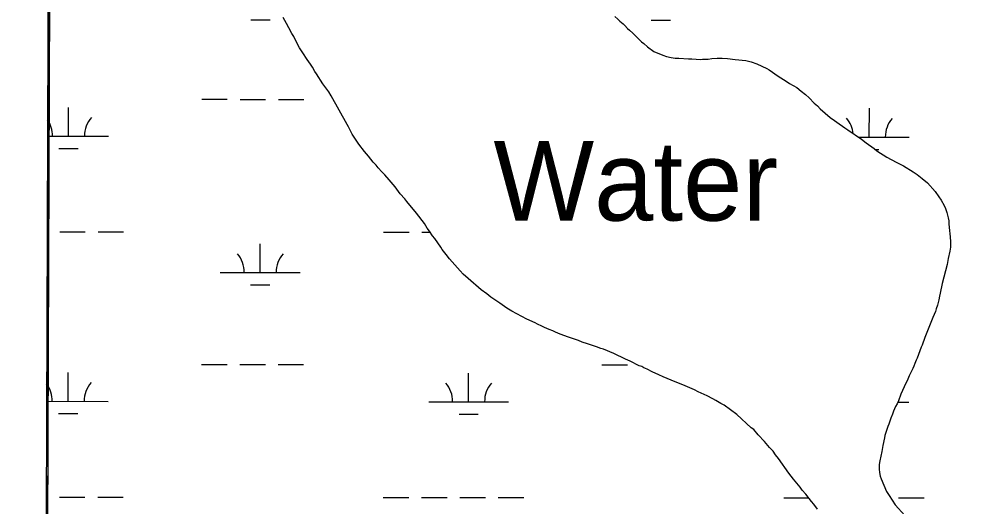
# Model space of a CAD drawing. Extents: x 3148686 to 3186545, y 916144 to 941516.
# Drawn here: x 3152922 to 3154122, y 931623 to 932235 of the extents above; entities that cross this region are included whole.
import ezdxf

# ---------------------------------------------------------------- set-up
doc = ezdxf.new("R2010")
doc.units = 0
for name, color, linetype in [('V-GRID-FRAM', 7, 'Continuous'), ('V-RIVR-IDEN', 7, 'Continuous'), ('V-SITE-VEGE', 7, 'Continuous'), ('V-TOPO-SHOR', 7, 'Continuous'), ('V-WETL-SWMP', 7, 'Continuous')]:
    doc.layers.add(name, color=color, linetype=linetype)

msp = doc.modelspace()

# ---------------------------------------------------------------- linework, layer by layer
at = {"layer": 'V-GRID-FRAM'}
msp.add_lwpolyline([(3152987.2, 939742.7), (3184296.3, 939644.8), (3184247.4, 921455.8), (3152922.4, 921553.7), (3152987.2, 939742.7)], dxfattribs=at)
at = {"layer": 'V-SITE-VEGE'}
for p, q in [((3152962, 932689.1), (3152952.2, 929936.2)), ((3153257.5, 932229.3), (3153253.5, 932237.1)), ((3153672.9, 932234.9), (3153675.3, 932232.5)), ((3153675.3, 932232.5), (3153679.4, 932229.1)), ((3153260.6, 932224.1), (3153257.5, 932229.3)), ((3153264.2, 932217), (3153260.6, 932224.1)), ((3153679.4, 932229.1), (3153681.7, 932226.7)), ((3153681.7, 932226.7), (3153684.8, 932223.2)), ((3153684.8, 932223.2), (3153687.5, 932221.2)), ((3153687.5, 932221.2), (3153691.8, 932217.1)), ((3153266.6, 932212.9), (3153264.2, 932217)), ((3153270.9, 932204.3), (3153266.6, 932212.9)), ((3153691.8, 932217.1), (3153702.3, 932206.4)), ((3153273.9, 932198.9), (3153270.9, 932204.3)), ((3153278, 932192.4), (3153273.9, 932198.9)), ((3153702.3, 932206.4), (3153705.3, 932204.4)), ((3153705.3, 932204.4), (3153710.1, 932200.3)), ((3153710.1, 932200.3), (3153717.8, 932194.4)), ((3153283.3, 932184.2), (3153278, 932192.4)), ((3153287.7, 932178.4), (3153283.3, 932184.2)), ((3153717.8, 932194.4), (3153729.3, 932189.6)), ((3153729.3, 932189.6), (3153733.8, 932188.2)), ((3153733.8, 932188.2), (3153739.5, 932186.8)), ((3153739.5, 932186.8), (3153744.6, 932186)), ((3153744.6, 932186), (3153749.4, 932186)), ((3153749.4, 932186), (3153761.6, 932184.9)), ((3153761.6, 932184.9), (3153765.7, 932184.9)), ((3153765.7, 932184.9), (3153771.1, 932184.5)), ((3153771.1, 932184.5), (3153775.9, 932184.4)), ((3153775.9, 932184.4), (3153778.9, 932184.7)), ((3153778.9, 932184.7), (3153786.1, 932184.7)), ((3153786.1, 932184.7), (3153790.5, 932185.3)), ((3153790.5, 932185.3), (3153797.3, 932186)), ((3153797.3, 932186), (3153803.4, 932185.9)), ((3153803.4, 932185.9), (3153810.2, 932185.5)), ((3153810.2, 932185.5), (3153819.7, 932184.1)), ((3153819.7, 932184.1), (3153833.3, 932182.9)), ((3153290.1, 932174.6), (3153287.7, 932178.4)), ((3153293.1, 932169.1), (3153290.1, 932174.6)), ((3153833.3, 932182.9), (3153840.1, 932181.2)), ((3153840.1, 932181.2), (3153847.2, 932178.7)), ((3153847.2, 932178.7), (3153859.4, 932172.9)), ((3153859.4, 932172.9), (3153862.5, 932171.1)), ((3153295.1, 932166.4), (3153293.1, 932169.1)), ((3153303.2, 932153.8), (3153295.1, 932166.4)), ((3153862.5, 932171.1), (3153873.9, 932163.2)), ((3153873.9, 932163.2), (3153883.8, 932157)), ((3153307.9, 932146.9), (3153303.2, 932153.8)), ((3153883.8, 932157), (3153887.8, 932154.3)), ((3153887.8, 932154.3), (3153897, 932149.1)), ((3153897, 932149.1), (3153902.7, 932144.6)), ((3153310.5, 932143.5), (3153307.9, 932146.9)), ((3153313.6, 932138.7), (3153310.5, 932143.5)), ((3153333.4, 932102.5), (3153313.6, 932138.7)), ((3153902.7, 932144.6), (3153908.1, 932140.2)), ((3153908.1, 932140.2), (3153912.5, 932136.1)), ((3153912.5, 932136.1), (3153918.9, 932129.5)), ((3153918.9, 932129.5), (3153922.9, 932126.1)), ((3153922.9, 932126.1), (3153926.6, 932122.3)), ((3153926.6, 932122.3), (3153939.1, 932111.4)), ((3153335, 932099.7), (3153333.4, 932102.5)), ((3153339.7, 932090.5), (3153335, 932099.7)), ((3153939.1, 932111.4), (3153944.2, 932107.9)), ((3153944.2, 932107.9), (3153947.2, 932105.5)), ((3153947.2, 932105.5), (3153957.4, 932098.6)), ((3153348.1, 932077.9), (3153339.7, 932090.5)), ((3153957.4, 932098.6), (3153961.1, 932095.9)), ((3153961.1, 932095.9), (3153978.3, 932084.2)), ((3153355.2, 932069), (3153348.1, 932077.9)), ((3153978.3, 932084.2), (3153984.1, 932079.7)), ((3153984.1, 932079.7), (3153994.2, 932072.5)), ((3153360.2, 932063.1), (3153355.2, 932069)), ((3153994.2, 932072.5), (3153997.6, 932069.8)), ((3153997.6, 932069.8), (3154010.1, 932061.5)), ((3153366, 932055.6), (3153360.2, 932063.1)), ((3153369.7, 932051.8), (3153366, 932055.6)), ((3153372.4, 932048.4), (3153369.7, 932051.8)), ((3154010.1, 932061.5), (3154021.6, 932055.3)), ((3154021.6, 932055.3), (3154030.8, 932050.8)), ((3153377.1, 932043.3), (3153372.4, 932048.4)), ((3153380.8, 932039.5), (3153377.1, 932043.3)), ((3153386.2, 932033.4), (3153380.8, 932039.5)), ((3154030.8, 932050.8), (3154042.9, 932043.5)), ((3154042.9, 932043.5), (3154048, 932040.1)), ((3154048, 932040.1), (3154054.4, 932035)), ((3153393.6, 932024.5), (3153386.2, 932033.4)), ((3154054.4, 932035), (3154060.8, 932029.5)), ((3154060.8, 932029.5), (3154070.6, 932018.5)), ((3153400, 932015.9), (3153393.6, 932024.5)), ((3153405.7, 932009.4), (3153400, 932015.9)), ((3154070.6, 932018.5), (3154075, 932012)), ((3153408.4, 932006), (3153405.7, 932009.4)), ((3153420.5, 931991.6), (3153408.4, 932006)), ((3154075, 932012), (3154078, 932007.9)), ((3154078, 932007.9), (3154082, 932001.1)), ((3153423.2, 931987.8), (3153420.5, 931991.6)), ((3154082, 932001.1), (3154083.7, 931997.3)), ((3154083.7, 931997.3), (3154085.4, 931992.2)), ((3154085.4, 931992.2), (3154087, 931985.4)), ((3153427.6, 931982.4), (3153423.2, 931987.8)), ((3153430.3, 931978.6), (3153427.6, 931982.4)), ((3154087, 931985.4), (3154087.7, 931982)), ((3154087.7, 931982), (3154087.6, 931977.9)), ((3153433.9, 931972.8), (3153430.3, 931978.6)), ((3153436.6, 931969), (3153433.9, 931972.8)), ((3153440.7, 931962.9), (3153436.6, 931969)), ((3154087.6, 931977.9), (3154088.3, 931973.5)), ((3154088.3, 931973.5), (3154089.2, 931961.6)), ((3153443.4, 931959.5), (3153440.7, 931962.9)), ((3153451.1, 931948.9), (3153443.4, 931959.5)), ((3154089.2, 931961.6), (3154089.8, 931955.5)), ((3153452.8, 931945.8), (3153451.1, 931948.9)), ((3153457.8, 931939.6), (3153452.8, 931945.8)), ((3154089, 931943.6), (3154086.9, 931934.7)), ((3154089.8, 931948.7), (3154089, 931943.6)), ((3154089.8, 931955.5), (3154089.8, 931948.7)), ((3153461.8, 931934.2), (3153457.8, 931939.6)), ((3153475, 931919.1), (3153461.8, 931934.2)), ((3154086.9, 931934.7), (3154085.5, 931926.9)), ((3154085.5, 931926.9), (3154079.5, 931903.2)), ((3153479, 931915), (3153475, 931919.1)), ((3153485.1, 931909.5), (3153479, 931915)), ((3153501.6, 931895.4), (3153485.1, 931909.5)), ((3154079.5, 931903.2), (3154077, 931891)), ((3153508.7, 931890.3), (3153501.6, 931895.4)), ((3153513.5, 931886.1), (3153508.7, 931890.3)), ((3153525, 931878.6), (3153513.5, 931886.1)), ((3154076, 931887.2), (3154075.3, 931882.8)), ((3154077, 931891), (3154076, 931887.2)), ((3153533.7, 931872.4), (3153525, 931878.6)), ((3153539.8, 931868.6), (3153533.7, 931872.4)), ((3154073.5, 931876), (3154071.8, 931871.3)), ((3154075.3, 931882.8), (3154073.5, 931876)), ((3153558.8, 931858.6), (3153539.8, 931868.6)), ((3154067.6, 931860.5), (3154057.6, 931835.4)), ((3154071.1, 931868.2), (3154067.6, 931860.5)), ((3154071.8, 931871.3), (3154071.1, 931868.2)), ((3153569, 931853.7), (3153558.8, 931858.6)), ((3153572, 931852), (3153569, 931853.7)), ((3153577.4, 931849.6), (3153572, 931852)), ((3153580.8, 931847.9), (3153577.4, 931849.6)), ((3153586.6, 931845.4), (3153580.8, 931847.9)), ((3153591.3, 931843.7), (3153586.6, 931845.4)), ((3153594.7, 931842), (3153591.3, 931843.7)), ((3153600.4, 931839.5), (3153594.7, 931842)), ((3153611, 931835.7), (3153600.4, 931839.5)), ((3153623.5, 931831.5), (3153611, 931835.7)), ((3153628.2, 931829.8), (3153623.5, 931831.5)), ((3153635, 931827.7), (3153628.2, 931829.8)), ((3153646.2, 931823.9), (3153635, 931827.7)), ((3153651.3, 931821.8), (3153646.2, 931823.9)), ((3154054.4, 931825.9), (3154053, 931823.2)), ((3154057.6, 931835.4), (3154054.4, 931825.9)), ((3153654.7, 931820.7), (3153651.3, 931821.8)), ((3153667.6, 931815.2), (3153654.7, 931820.7)), ((3153682.5, 931808.3), (3153667.6, 931815.2)), ((3154053, 931823.2), (3154048.2, 931809.6)), ((3153688.2, 931805.8), (3153682.5, 931808.3)), ((3153699.7, 931800), (3153688.2, 931805.8)), ((3153702.7, 931799.2), (3153699.7, 931800)), ((3154045.1, 931802.9), (3154043.7, 931799.5)), ((3154046.8, 931806.9), (3154045.1, 931802.9)), ((3154048.2, 931809.6), (3154046.8, 931806.9)), ((3153705.4, 931797.5), (3153702.7, 931799.2)), ((3153709.5, 931795.7), (3153705.4, 931797.5)), ((3153715.9, 931792.3), (3153709.5, 931795.7)), ((3153724.4, 931788.8), (3153715.9, 931792.3)), ((3153729.8, 931786.1), (3153724.4, 931788.8)), ((3154042.6, 931796.4), (3154038.1, 931787.3)), ((3154043.7, 931799.5), (3154042.6, 931796.4)), ((3153739.6, 931781.9), (3153729.8, 931786.1)), ((3153757.2, 931775), (3153739.6, 931781.9)), ((3154036.4, 931783.2), (3154031.9, 931773.7)), ((3154038.1, 931787.3), (3154036.4, 931783.2)), ((3153769.1, 931769.8), (3153757.2, 931775)), ((3153773.5, 931767.3), (3153769.1, 931769.8)), ((3153785, 931762.1), (3153773.5, 931767.3)), ((3154027.7, 931764.2), (3154024.6, 931756.1)), ((3154031.9, 931773.7), (3154027.7, 931764.2)), ((3153791.8, 931758.7), (3153785, 931762.1)), ((3153795.5, 931756.3), (3153791.8, 931758.7)), ((3153801.9, 931752.5), (3153795.5, 931756.3)), ((3153806, 931750.4), (3153801.9, 931752.5)), ((3154022.9, 931752.4), (3154020.8, 931749)), ((3154024.6, 931756.1), (3154022.9, 931752.4)), ((3153814.1, 931744.9), (3153806, 931750.4)), ((3153821.9, 931738.7), (3153814.1, 931744.9)), ((3154018.4, 931743.2), (3154017, 931739.2)), ((3154020.8, 931749), (3154018.4, 931743.2)), ((3153840.1, 931722.3), (3153821.9, 931738.7)), ((3154014.9, 931734.1), (3154012.5, 931726.6)), ((3154017, 931739.2), (3154014.9, 931734.1)), ((3153843.5, 931719.9), (3153840.1, 931722.3)), ((3153848.9, 931713.4), (3153843.5, 931719.9)), ((3154011.1, 931723.6), (3154007.6, 931712.7)), ((3154012.5, 931726.6), (3154011.1, 931723.6)), ((3153856.6, 931705.1), (3153848.9, 931713.4)), ((3153858.6, 931702.4), (3153856.6, 931705.1)), ((3154007.2, 931709.7), (3154004.8, 931699.8)), ((3154007.6, 931712.7), (3154007.2, 931709.7)), ((3153863, 931697.6), (3153858.6, 931702.4)), ((3153867.7, 931692.8), (3153863, 931697.6)), ((3153870.4, 931688.4), (3153867.7, 931692.8)), ((3154003.7, 931692.4), (3154001.2, 931680.8)), ((3154004.8, 931699.8), (3154003.7, 931692.4)), ((3153874.1, 931683.6), (3153870.4, 931688.4)), ((3153887.2, 931665.4), (3153874.1, 931683.6)), ((3154001.2, 931680.8), (3154000.5, 931676.1)), ((3154000.5, 931676.1), (3154000.5, 931670.3)), ((3154000.5, 931670.3), (3154000.8, 931665.9)), ((3153892.9, 931657.9), (3153887.2, 931665.4)), ((3153901.3, 931647.7), (3153892.9, 931657.9)), ((3154000.8, 931665.9), (3154001.7, 931661.4)), ((3154001.7, 931661.4), (3154002.7, 931658)), ((3154002.7, 931658), (3154009.7, 931642.3)), ((3153904, 931643.9), (3153901.3, 931647.7)), ((3153908.4, 931638.8), (3153904, 931643.9)), ((3153915.5, 931629.9), (3153908.4, 931638.8)), ((3154009.7, 931642.3), (3154012.8, 931637.2)), ((3154012.8, 931637.2), (3154020.5, 931625.6)), ((3153918.5, 931626.4), (3153915.5, 931629.9)), ((3153922.9, 931619.9), (3153918.5, 931626.4)), ((3154020.5, 931625.6), (3154032.6, 931612.2))]:
    msp.add_line(p, q, dxfattribs=at)
at = {"layer": 'V-TOPO-SHOR'}
for points in [[(3153739.6, 931781.9), (3153729.8, 931786.1), (3153724.4, 931788.8), (3153715.9, 931792.3), (3153709.5, 931795.7), (3153705.4, 931797.5), (3153702.7, 931799.2), (3153699.7, 931800), (3153688.2, 931805.8), (3153682.5, 931808.3), (3153667.6, 931815.2), (3153654.7, 931820.7), (3153651.3, 931821.8), (3153646.2, 931823.9), (3153635, 931827.7), (3153628.2, 931829.8), (3153623.5, 931831.5), (3153611, 931835.7), (3153600.4, 931839.5), (3153594.7, 931842), (3153591.3, 931843.7), (3153586.6, 931845.4), (3153580.8, 931847.9), (3153577.4, 931849.6), (3153572, 931852), (3153569, 931853.7), (3153558.8, 931858.6), (3153539.8, 931868.6), (3153533.7, 931872.4), (3153525, 931878.6), (3153513.5, 931886.1), (3153508.7, 931890.3), (3153501.6, 931895.4), (3153485.1, 931909.5), (3153479, 931915), (3153475, 931919.1), (3153461.8, 931934.2), (3153457.8, 931939.6), (3153452.8, 931945.8), (3153451.1, 931948.9), (3153443.4, 931959.5), (3153440.7, 931962.9), (3153436.6, 931969), (3153433.9, 931972.8), (3153430.3, 931978.6), (3153427.6, 931982.4), (3153423.2, 931987.8), (3153420.5, 931991.6), (3153408.4, 932006), (3153405.7, 932009.4), (3153400, 932015.9), (3153393.6, 932024.5), (3153386.2, 932033.4), (3153380.8, 932039.5), (3153377.1, 932043.3), (3153372.4, 932048.4), (3153369.7, 932051.8), (3153366, 932055.6), (3153360.2, 932063.1), (3153355.2, 932069), (3153348.1, 932077.9), (3153339.7, 932090.5), (3153335, 932099.7), (3153333.4, 932102.5), (3153313.6, 932138.7), (3153310.5, 932143.5), (3153307.9, 932146.9), (3153303.2, 932153.8), (3153295.1, 932166.4), (3153293.1, 932169.1), (3153290.1, 932174.6), (3153287.7, 932178.4), (3153283.3, 932184.2), (3153278, 932192.4), (3153273.9, 932198.9), (3153270.9, 932204.3), (3153266.6, 932212.9), (3153264.2, 932217), (3153260.6, 932224.1), (3153257.5, 932229.3), (3153253.5, 932237.1)], [(3153668.9, 932238.3), (3153672.9, 932234.9), (3153675.3, 932232.5), (3153679.4, 932229.1), (3153681.7, 932226.7), (3153684.8, 932223.2), (3153687.5, 932221.2), (3153691.8, 932217.1), (3153702.3, 932206.4), (3153705.3, 932204.4), (3153710.1, 932200.3), (3153717.8, 932194.4), (3153729.3, 932189.6), (3153733.8, 932188.2), (3153739.5, 932186.8), (3153744.6, 932186), (3153749.4, 932186), (3153761.6, 932184.9), (3153765.7, 932184.9), (3153771.1, 932184.5), (3153775.9, 932184.4), (3153778.9, 932184.7), (3153786.1, 932184.7), (3153790.5, 932185.3), (3153797.3, 932186), (3153803.4, 932185.9), (3153810.2, 932185.5), (3153819.7, 932184.1), (3153833.3, 932182.9), (3153840.1, 932181.2), (3153847.2, 932178.7), (3153859.4, 932172.9), (3153862.5, 932171.1), (3153873.9, 932163.2), (3153883.8, 932157), (3153887.8, 932154.3), (3153897, 932149.1), (3153902.7, 932144.6), (3153908.1, 932140.2), (3153912.5, 932136.1), (3153918.9, 932129.5), (3153922.9, 932126.1), (3153926.6, 932122.3), (3153939.1, 932111.4), (3153944.2, 932107.9), (3153947.2, 932105.5), (3153957.4, 932098.6), (3153961.1, 932095.9), (3153978.3, 932084.2), (3153984.1, 932079.7), (3153994.2, 932072.5), (3153997.6, 932069.8), (3154010.1, 932061.5), (3154021.6, 932055.3), (3154030.8, 932050.8), (3154042.9, 932043.5), (3154048, 932040.1), (3154054.4, 932035), (3154060.8, 932029.5), (3154070.6, 932018.5), (3154075, 932012), (3154078, 932007.9), (3154082, 932001.1), (3154083.7, 931997.3), (3154085.4, 931992.2), (3154087, 931985.4), (3154087.7, 931982), (3154087.6, 931977.9), (3154088.3, 931973.5), (3154089.2, 931961.6), (3154089.8, 931955.5), (3154089.8, 931948.7), (3154089, 931943.6), (3154086.9, 931934.7), (3154085.5, 931926.9), (3154079.5, 931903.2), (3154077, 931891), (3154076, 931887.2), (3154075.3, 931882.8), (3154073.5, 931876), (3154071.8, 931871.3), (3154071.1, 931868.2), (3154067.6, 931860.5), (3154057.6, 931835.4), (3154054.4, 931825.9), (3154053, 931823.2), (3154048.2, 931809.6), (3154046.8, 931806.9), (3154045.1, 931802.9)], [(3154045.1, 931802.9), (3154043.7, 931799.5), (3154042.6, 931796.4), (3154038.1, 931787.3), (3154036.4, 931783.2), (3154031.9, 931773.7), (3154027.7, 931764.2), (3154024.6, 931756.1), (3154022.9, 931752.4), (3154020.8, 931749), (3154018.4, 931743.2), (3154017, 931739.2), (3154014.9, 931734.1), (3154012.5, 931726.6), (3154011.1, 931723.6), (3154007.6, 931712.7), (3154007.2, 931709.7), (3154004.8, 931699.8), (3154003.7, 931692.4), (3154001.2, 931680.8), (3154000.5, 931676.1), (3154000.5, 931670.3), (3154000.8, 931665.9), (3154001.7, 931661.4), (3154002.7, 931658), (3154009.7, 931642.3), (3154012.8, 931637.2), (3154020.5, 931625.6), (3154032.6, 931612.2)], [(3153922.9, 931619.9), (3153918.5, 931626.4), (3153915.5, 931629.9), (3153908.4, 931638.8), (3153904, 931643.9), (3153901.3, 931647.7), (3153892.9, 931657.9), (3153887.2, 931665.4), (3153874.1, 931683.6), (3153870.4, 931688.4), (3153867.7, 931692.8), (3153863, 931697.6), (3153858.6, 931702.4), (3153856.6, 931705.1), (3153848.9, 931713.4), (3153843.5, 931719.9), (3153840.1, 931722.3), (3153821.9, 931738.7), (3153814.1, 931744.9), (3153806, 931750.4), (3153801.9, 931752.5), (3153795.5, 931756.3), (3153791.8, 931758.7), (3153785, 931762.1), (3153773.5, 931767.3), (3153769.1, 931769.8), (3153757.2, 931775), (3153739.6, 931781.9)]]:
    msp.add_lwpolyline(points, dxfattribs=at)
at = {"layer": 'V-WETL-SWMP'}
for p, q in [((3153212.9, 932234.2), (3153236.9, 932234.2)), ((3153714.8, 932233.7), (3153738.8, 932233.7)), ((3152984.2, 932088), (3152984.3, 932124)), ((3153151.3, 932134.3), (3153183.3, 932134.3)), ((3153199.3, 932134.2), (3153231.3, 932134.2)), ((3153247.3, 932134.2), (3153279.3, 932134.2)), ((3153988, 932087), (3153988.1, 932123)), ((3152957.9, 932088.1), (3153034.2, 932088)), ((3153974.2, 932087), (3154038, 932086.9)), ((3152972.2, 932072.6), (3152996.2, 932072.6)), ((3153995.4, 932071.5), (3154000, 932071.5)), ((3152973.3, 931968), (3153005.3, 931967.9)), ((3153021.3, 931967.9), (3153053.3, 931967.9)), ((3153379.2, 931967.6), (3153411.2, 931967.5)), ((3153427.2, 931967.5), (3153437.6, 931967.5)), ((3153224.5, 931917), (3153224.6, 931953)), ((3153174.5, 931917), (3153274.5, 931916.9)), ((3153212.5, 931901.6), (3153236.5, 931901.5)), ((3153151, 931801.6), (3153183, 931801.6)), ((3153199, 931801.6), (3153231, 931801.5)), ((3153247, 931801.5), (3153279, 931801.5)), ((3153652.9, 931801.1), (3153684.9, 931801.1)), ((3152983.9, 931755.4), (3152983.9, 931791.4)), ((3153485.8, 931754.8), (3153485.8, 931790.8)), ((3152956.7, 931755.4), (3153033.9, 931755.3)), ((3153435.8, 931754.9), (3153535.8, 931754.8)), ((3154023.8, 931754.3), (3154037.7, 931754.3)), ((3152971.9, 931739.9), (3152995.9, 931739.9)), ((3153473.8, 931739.4), (3153497.8, 931739.4)), ((3152956.3, 931635.3), (3152956.9, 931635.3)), ((3152972.9, 931635.3), (3153004.9, 931635.3)), ((3153020.9, 931635.3), (3153052.9, 931635.2)), ((3153378.8, 931634.9), (3153410.8, 931634.8)), ((3153426.8, 931634.8), (3153458.8, 931634.8)), ((3153474.8, 931634.8), (3153506.8, 931634.7)), ((3153522.8, 931634.7), (3153554.8, 931634.7)), ((3153880.7, 931634.3), (3153911.9, 931634.3)), ((3154024.7, 931634.2), (3154056.7, 931634.2))]:
    msp.add_line(p, q, dxfattribs=at)
for points in [[(3152960, 932691.2), (3152950.2, 929936.4)], [(3153922.9, 931619.9), (3153918.5, 931626.4), (3153915.5, 931629.9), (3153908.4, 931638.8), (3153904, 931643.9), (3153901.3, 931647.7), (3153892.9, 931657.9), (3153887.2, 931665.4), (3153874.1, 931683.6), (3153870.4, 931688.4), (3153867.7, 931692.8), (3153863, 931697.6), (3153858.6, 931702.4), (3153856.6, 931705.1), (3153848.9, 931713.3), (3153843.5, 931719.9), (3153840.1, 931722.3), (3153821.9, 931738.7), (3153814.1, 931744.9), (3153806, 931750.4), (3153801.9, 931752.5), (3153795.5, 931756.3), (3153791.8, 931758.7), (3153785, 931762.1), (3153773.5, 931767.3), (3153769.1, 931769.8), (3153757.2, 931774.9), (3153739.6, 931781.9), (3153729.8, 931786.1), (3153724.4, 931788.8), (3153715.9, 931792.3), (3153709.5, 931795.7), (3153705.4, 931797.5), (3153702.7, 931799.2), (3153699.7, 931800), (3153688.2, 931805.8), (3153682.5, 931808.3), (3153667.6, 931815.2), (3153654.7, 931820.7), (3153651.3, 931821.8), (3153646.2, 931823.9), (3153635, 931827.7), (3153628.2, 931829.8), (3153623.5, 931831.5), (3153611, 931835.7), (3153600.5, 931839.5), (3153594.7, 931842), (3153591.3, 931843.7), (3153586.6, 931845.4), (3153580.8, 931847.9), (3153577.4, 931849.6), (3153572, 931852), (3153569, 931853.7), (3153558.8, 931858.6), (3153539.8, 931868.6), (3153533.7, 931872.4), (3153525, 931878.6), (3153513.5, 931886.1), (3153508.7, 931890.3), (3153501.6, 931895.4), (3153485.1, 931909.5), (3153479, 931915), (3153475, 931919.1), (3153461.8, 931934.2), (3153457.8, 931939.6), (3153452.8, 931945.8), (3153451.1, 931948.9), (3153443.4, 931959.5), (3153440.7, 931962.9), (3153436.6, 931969), (3153433.9, 931972.8), (3153430.3, 931978.6), (3153427.6, 931982.4), (3153423.2, 931987.8), (3153420.5, 931991.6), (3153408.4, 932006), (3153405.7, 932009.4), (3153400, 932015.9), (3153393.6, 932024.5), (3153386.2, 932033.4), (3153380.8, 932039.5), (3153377.1, 932043.3), (3153372.4, 932048.4), (3153369.7, 932051.8), (3153366, 932055.6), (3153360.2, 932063.1), (3153355.2, 932069), (3153348.1, 932077.9), (3153339.7, 932090.5), (3153335, 932099.7), (3153333.4, 932102.5), (3153313.6, 932138.7), (3153310.5, 932143.5), (3153307.9, 932146.9), (3153303.2, 932153.8), (3153295.1, 932166.4), (3153293.1, 932169.1), (3153290.1, 932174.6), (3153287.7, 932178.4), (3153283.3, 932184.2), (3153278, 932192.4), (3153273.9, 932198.9), (3153270.9, 932204.3), (3153266.6, 932212.9), (3153264.2, 932217), (3153260.6, 932224.1), (3153257.5, 932229.3), (3153253.5, 932237.1)], [(3153668.9, 932238.3), (3153672.9, 932234.9), (3153675.3, 932232.5), (3153679.4, 932229.1), (3153681.7, 932226.7), (3153684.8, 932223.2), (3153687.5, 932221.2), (3153691.8, 932217.1), (3153702.3, 932206.4), (3153705.3, 932204.4), (3153710.1, 932200.3), (3153717.8, 932194.4), (3153729.3, 932189.6), (3153733.8, 932188.2), (3153739.5, 932186.8), (3153744.6, 932186), (3153749.4, 932186), (3153761.6, 932184.9), (3153765.7, 932184.9), (3153771.1, 932184.5), (3153775.9, 932184.4), (3153778.9, 932184.7), (3153786.1, 932184.7), (3153790.5, 932185.3), (3153797.3, 932186), (3153803.4, 932185.9), (3153810.2, 932185.5), (3153819.7, 932184.1), (3153833.3, 932182.9), (3153840.1, 932181.2), (3153847.2, 932178.7), (3153859.4, 932172.9), (3153862.5, 932171.1), (3153873.9, 932163.2), (3153883.8, 932157), (3153887.8, 932154.3), (3153897, 932149.1), (3153902.7, 932144.6), (3153908.1, 932140.2), (3153912.5, 932136.1), (3153918.9, 932129.5), (3153922.9, 932126.1), (3153926.6, 932122.3), (3153939.1, 932111.4), (3153944.2, 932107.9), (3153947.2, 932105.5), (3153957.4, 932098.6), (3153961.1, 932095.9), (3153978.3, 932084.2), (3153984.1, 932079.7), (3153994.2, 932072.5), (3153997.6, 932069.8), (3154010.1, 932061.5), (3154021.6, 932055.3), (3154030.8, 932050.8), (3154042.9, 932043.5), (3154048, 932040.1), (3154054.4, 932035), (3154060.8, 932029.5), (3154070.6, 932018.5), (3154075, 932012), (3154078, 932007.9), (3154082, 932001.1), (3154083.7, 931997.3), (3154085.4, 931992.2), (3154087, 931985.4), (3154087.7, 931982), (3154087.6, 931977.9), (3154088.3, 931973.5), (3154089.2, 931961.6), (3154089.8, 931955.5), (3154089.8, 931948.7), (3154089, 931943.6), (3154086.9, 931934.7), (3154085.5, 931926.9), (3154079.5, 931903.2), (3154077, 931891), (3154076, 931887.2), (3154075.3, 931882.8), (3154073.5, 931876), (3154071.8, 931871.3), (3154071.1, 931868.2), (3154067.6, 931860.5), (3154057.6, 931835.4), (3154054.4, 931825.9), (3154053, 931823.2), (3154048.2, 931809.6), (3154046.8, 931806.9), (3154045.1, 931802.8), (3154043.7, 931799.5), (3154042.6, 931796.4), (3154038.1, 931787.3), (3154036.4, 931783.2), (3154031.9, 931773.7), (3154027.7, 931764.2), (3154024.6, 931756.1), (3154022.9, 931752.4), (3154020.8, 931749), (3154018.4, 931743.2), (3154017, 931739.2), (3154014.9, 931734.1), (3154012.5, 931726.6), (3154011.1, 931723.6), (3154007.6, 931712.7), (3154007.2, 931709.7), (3154004.8, 931699.8), (3154003.7, 931692.4), (3154001.2, 931680.8), (3154000.5, 931676.1), (3154000.5, 931670.3), (3154000.8, 931665.9), (3154001.7, 931661.4), (3154002.7, 931658), (3154009.7, 931642.3), (3154012.8, 931637.2), (3154020.5, 931625.6), (3154032.6, 931612.2)]]:
    msp.add_lwpolyline(points, dxfattribs=at)
for centre, start, end in [((3153039.5, 932088.5), 139.1678, 180.7115), ((3152929, 932088.6), 359.1678, 34.7506), ((3153932.8, 932087.5), 6.1983, 40.7115), ((3154043.3, 932087.4), 139.1678, 180.7115), ((3153169.3, 931917.5), 359.1678, 40.7115), ((3153279.8, 931917.4), 139.1678, 180.7115), ((3152928.6, 931755.9), 359.1678, 37.054), ((3153039.1, 931755.8), 139.1678, 180.7115), ((3153430.5, 931755.4), 359.1678, 40.7115), ((3153541, 931755.3), 139.1678, 180.7115)]:
    msp.add_arc(centre, 35.2, start, end, dxfattribs=at)

# ---------------------------------------------------------------- texts
at = {"layer": 'V-RIVR-IDEN'}
msp.add_text('Water', height=100, dxfattribs=at).set_placement((3153516.9, 931982.1))

doc.saveas('drawing.dxf')
